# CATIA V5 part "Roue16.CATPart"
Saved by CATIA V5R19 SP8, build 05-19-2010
Part number: Roue16
Bounding box of the stored display mesh (mm): x -150 to -130, y -73.814 to -13.814, z 50.201 to 110.201
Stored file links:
  G:\EU_thinkMotion\CFAO_2010\MMS_groupe2\MMS_groupe2\A reprendre\jcauchy\Roue16.CATPart
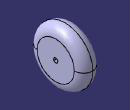
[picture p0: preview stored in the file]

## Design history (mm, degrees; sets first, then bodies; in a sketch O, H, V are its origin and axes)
Parameters
  Rayonroue_roue16 = 30 mm
  Rayoncongeroue_roue16 = 10 mm
  Rayonfixation_roue16 = 2.5 mm
  Largeurroue_roue16 = 10 mm
Set1
  Plane1: stored without definition
  Sketch1 on Plane1, origin (-140, 0, 0), H (0, 1, 0), V (0, 0, 1)
    circle A1 centre (-43.8144, 80.2007) radius 30
    point P1 (-43.8144, 80.2007)
    reference projected point E1 (-43.8144, 80.2007) from Point1
    radius A1 = 30 {= Rayonroue_roue16}
    distance P1 E1 = 0
  Point1: stored without definition
Body1 (main body)
  Pad1: profile Sketch1, direction (1, 0, 0), length 10 {= Largeurroue_roue16}, mirrored extent
  Fillet1: radius 10 {= Rayoncongeroue_roue16}, on edge [start face of Pad1 | face of Pad1 from Sketch1.A1]
  Fillet2: radius 10 {= Rayoncongeroue_roue16}, on edge [face of Pad1 from Sketch1.A1 | end face of Pad1]
  Sketch2 on start face of Pad1, origin (-150, -43.8144, 80.2007), H (0, 1, 0), V (0, 0, -1)
    point P1 (0, 0)
  Hole1: placed by Sketch2, at (-150, -43.8144, 80.2007) direction (1, 0, 0), diameter 5 {= Rayonfixation_roue16 *2}, through (limit type 3)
